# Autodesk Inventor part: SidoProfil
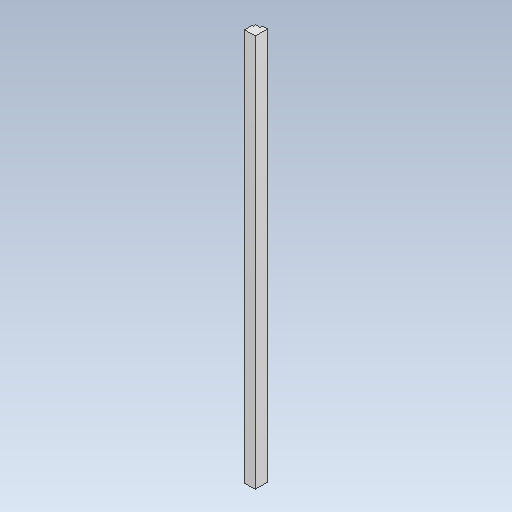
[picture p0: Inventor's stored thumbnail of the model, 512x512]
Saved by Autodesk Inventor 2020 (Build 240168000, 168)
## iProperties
Created: 2019-06
Part Number: SidoProfil
Material: Aluminum
Document SubType Name: Modeling
Designer: cl
Density: 2.7 g/cm^3
Appearance: Satin
Author: cl
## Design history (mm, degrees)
sketch "Sketch1"
  geometry: L1 (0, 0)-(87, 0); L2 (87, 0)-(87, -60); L3 (87, -60)-(77, -60); L4 (77, -60)-(77, -80); L5 (77, -80)-(40, -80); L6 (40, -80)-(40, -100); L7 (40, -100)-(0, -100); L8 (0, -100)-(0, 0)
  constraints: 16 end point, 5 perpendicular, 2 horizontal
  dimensions: "d0" = 87 distance of L1.start L1.end; "d1" = 60 distance of L1.end L2.end; "d2" = 10 distance of L2.end L3.end; "d3" = 20 distance of L3.end L4.end; "d4" = 37 distance of L4.end L5.end; "d5" = 20 distance of L5.end L6.end; "d6" = 40 distance of L6.end L7.end
extrude "Extrusion1" new body sketch "Sketch1" distance "d7" = 3190 (computed from Daghöjd); taper "d8" = 0 deg
body "Solid1"
